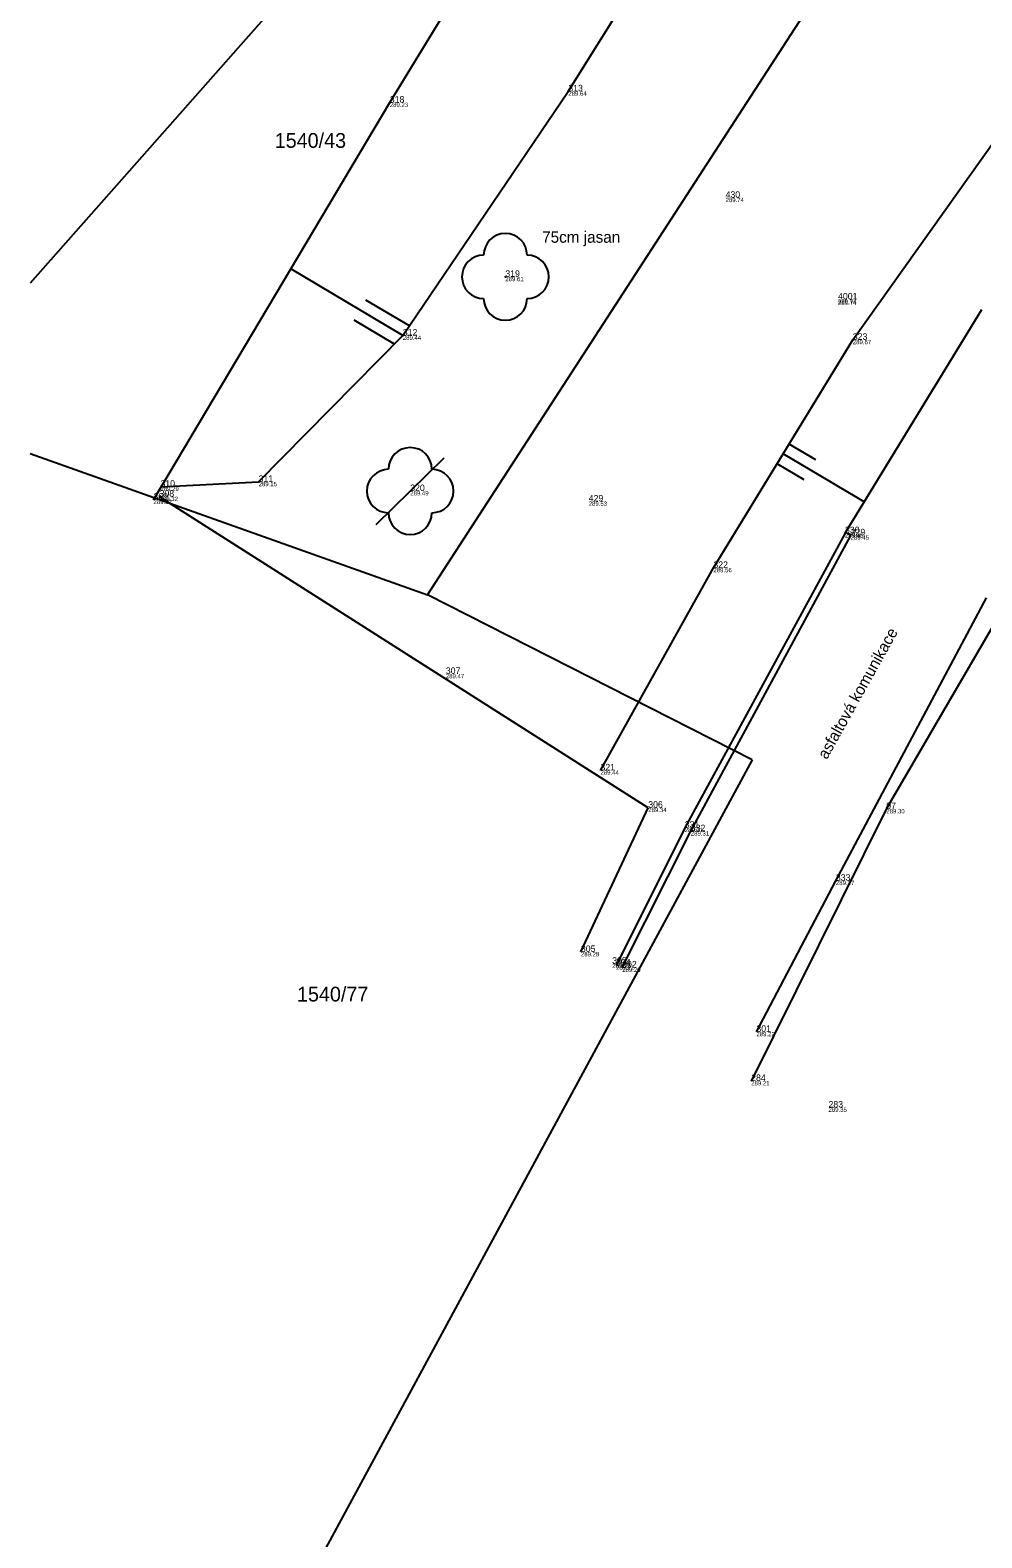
# Model space of a CAD drawing. Extents: x -805057 to -804930, y -994399 to -994240.
# Drawn here: x -805055.46 to -805033.55, y -994342.6 to -994307.89 of the extents above; entities that cross this region are included whole.
import ezdxf

# ---------------------------------------------------------------- set-up
doc = ezdxf.new("R2010")
doc.units = 0
for name, color, linetype in [('bod cislo', 7, 'Continuous'), ('bod pozice', 7, 'Continuous'), ('bod výška', 7, 'Continuous'), ('Katastralni mapa', 7, 'Continuous'), ('komunikace', 7, 'Continuous'), ('plot', 7, 'Continuous'), ('popis', 7, 'Continuous'), ('strom', 7, 'Continuous'), ('svah', 7, 'Continuous'), ('šrafy', 7, 'Continuous')]:
    doc.layers.add(name, color=color, linetype=linetype)

msp = doc.modelspace()

# ---------------------------------------------------------------- linework, layer by layer
at = {"layer": 'bod pozice'}
for p, q in [((-805043.07, -994309.3), (-805043.07, -994309.3)), ((-805047.18, -994309.56), (-805047.18, -994309.56)), ((-805039.45, -994311.75), (-805039.45, -994311.75)), ((-805044.52, -994313.57), (-805044.52, -994313.57)), ((-805036.86, -994314.09), (-805036.86, -994314.09)), ((-805033.55, -994314.32), (-805033.55, -994314.32)), ((-805046.88, -994314.92), (-805046.88, -994314.92)), ((-805036.52, -994315.02), (-805036.52, -994315.02)), ((-805052.46, -994318.4), (-805052.46, -994318.4)), ((-805050.2, -994318.29), (-805050.2, -994318.29)), ((-805052.62, -994318.7), (-805052.62, -994318.7)), ((-805052.48, -994318.63), (-805052.48, -994318.63)), ((-805046.71, -994318.5), (-805046.71, -994318.5)), ((-805042.6, -994318.74), (-805042.6, -994318.74)), ((-805036.7, -994319.47), (-805036.7, -994319.47)), ((-805036.57, -994319.52), (-805036.57, -994319.52)), ((-805039.73, -994320.27), (-805039.73, -994320.27)), ((-805045.89, -994322.71), (-805045.89, -994322.71)), ((-805042.33, -994324.93), (-805042.33, -994324.93)), ((-805041.23, -994325.79), (-805041.23, -994325.79)), ((-805035.75, -994325.82), (-805035.75, -994325.82)), ((-805040.39, -994326.25), (-805040.39, -994326.25)), ((-805040.25, -994326.33), (-805040.25, -994326.33)), ((-805036.91, -994327.47), (-805036.91, -994327.47)), ((-805042.78, -994329.11), (-805042.78, -994329.11)), ((-805042.06, -994329.38), (-805042.06, -994329.38)), ((-805041.97, -994329.42), (-805041.97, -994329.42)), ((-805041.83, -994329.47), (-805041.83, -994329.47)), ((-805038.74, -994330.95), (-805038.74, -994330.95)), ((-805038.86, -994332.08), (-805038.86, -994332.08)), ((-805037.08, -994332.69), (-805037.08, -994332.69))]:
    msp.add_line(p, q, dxfattribs=at)
at = {"layer": 'Katastralni mapa'}
for points in [[(-805037.93, -994293.88), (-805055.46, -994313.714)], [(-805046.31, -994320.89), (-805034.44, -994302.58)], [(-805055.46, -994317.638), (-805046.31, -994320.89)], [(-805038.84, -994324.69), (-805046.31, -994320.89)], [(-805038.84, -994324.69), (-805052.05, -994349.11)]]:
    msp.add_lwpolyline(points, dxfattribs=at)
at = {"layer": 'komunikace'}
for p, q in [((-805036.691, -994319.454), (-805033.55, -994314.32)), ((-805036.7, -994319.47), (-805040.39, -994326.25)), ((-805036.7, -994319.47), (-805036.691, -994319.454)), ((-805036.57, -994319.52), (-805036.691, -994319.454)), ((-805040.25, -994326.33), (-805036.57, -994319.52)), ((-805036.91, -994327.47), (-805033.44, -994320.96)), ((-805040.39, -994326.25), (-805041.97, -994329.42)), ((-805041.83, -994329.47), (-805040.25, -994326.33)), ((-805038.74, -994330.95), (-805036.91, -994327.47))]:
    msp.add_line(p, q, dxfattribs=at)
at = {"layer": 'plot'}
for p, q in [((-805047.18, -994309.56), (-805040.53, -994298.67)), ((-805052.62, -994318.7), (-805047.18, -994309.56)), ((-805031.37, -994318.3), (-805035.75, -994325.82)), ((-805041.23, -994325.79), (-805052.48, -994318.63)), ((-805042.78, -994329.11), (-805041.23, -994325.79)), ((-805035.75, -994325.82), (-805038.86, -994332.08))]:
    msp.add_line(p, q, dxfattribs=at)
at = {"layer": 'strom'}
for p, q in [((-805046.71, -994318.5), (-805045.928, -994317.732)), ((-805047.492, -994319.268), (-805046.71, -994318.5))]:
    msp.add_line(p, q, dxfattribs=at)
for centre in [(-805044.52, -994313.57), (-805046.71, -994318.5)]:
    msp.add_circle(centre, 0.0005, dxfattribs=at)
for centre, start, end in [((-805044.52, -994313.07), 0, 180), ((-805045.02, -994313.57), 90, 270), ((-805044.02, -994313.57), 270, 90), ((-805044.52, -994314.07), 180, 360), ((-805046.71, -994318), 0, 180), ((-805047.21, -994318.5), 90, 270), ((-805046.21, -994318.5), 270, 90), ((-805046.71, -994319), 180, 360)]:
    msp.add_arc(centre, 0.5, start, end, dxfattribs=at)
at = {"layer": 'svah'}
for p, q in [((-805043.07, -994309.3), (-805040.36, -994304.95)), ((-805046.88, -994314.92), (-805043.07, -994309.3)), ((-805036.52, -994315.02), (-805032.96, -994310.02)), ((-805050.2, -994318.29), (-805046.88, -994314.92)), ((-805039.73, -994320.27), (-805036.52, -994315.02)), ((-805052.46, -994318.4), (-805050.2, -994318.29)), ((-805042.33, -994324.93), (-805039.73, -994320.27))]:
    msp.add_line(p, q, dxfattribs=at)
at = {"layer": 'šrafy'}
for p, q in [((-805046.88, -994314.92), (-805049.458, -994313.388)), ((-805046.73, -994314.699), (-805047.73, -994314.105)), ((-805047.073, -994315.116), (-805048.003, -994314.564)), ((-805036.262, -994318.752), (-805038.125, -994317.645)), ((-805037.369, -994317.784), (-805037.986, -994317.418)), ((-805037.643, -994318.243), (-805038.265, -994317.873))]:
    msp.add_line(p, q, dxfattribs=at)

# ---------------------------------------------------------------- texts
at = {"layer": 'bod cislo'}
for s, p in [('318    ', (-805047.18, -994309.56)), ('313    ', (-805043.07, -994309.3)), ('430    ', (-805039.45, -994311.75)), ('319    ', (-805044.52, -994313.57)), ('4001    ', (-805036.86, -994314.09)), ('312    ', (-805046.88, -994314.92)), ('323    ', (-805036.52, -994315.02)), ('310    ', (-805052.46, -994318.4)), ('311    ', (-805050.2, -994318.29)), ('320    ', (-805046.71, -994318.5)), ('309    ', (-805052.62, -994318.7)), ('308    ', (-805052.48, -994318.63)), ('429    ', (-805042.6, -994318.74)), ('330    ', (-805036.7, -994319.47)), ('329    ', (-805036.57, -994319.52)), ('322    ', (-805039.73, -994320.27)), ('307    ', (-805045.89, -994322.71)), ('321    ', (-805042.33, -994324.93)), ('306    ', (-805041.23, -994325.79)), ('97    ', (-805035.75, -994325.82)), ('331    ', (-805040.39, -994326.25)), ('332    ', (-805040.25, -994326.33)), ('333    ', (-805036.91, -994327.47)), ('305    ', (-805042.78, -994329.11)), ('303    ', (-805042.06, -994329.38)), ('304    ', (-805041.97, -994329.42)), ('302    ', (-805041.83, -994329.47)), ('301    ', (-805038.74, -994330.95)), ('284    ', (-805038.86, -994332.08)), ('283    ', (-805037.08, -994332.69))]:
    msp.add_text(s, height=0.15, dxfattribs=at).set_placement(p)
at = {"layer": 'bod výška'}
for s, p in [('289.64  ', (-805043.07, -994309.4)), ('289.23  ', (-805047.18, -994309.66)), ('289.74  ', (-805039.45, -994311.85)), ('289.61  ', (-805044.52, -994313.67)), ('289.74  ', (-805036.86, -994314.19)), ('289.74  ', (-805036.86, -994314.22)), ('289.44  ', (-805046.88, -994315.02)), ('289.67  ', (-805036.52, -994315.12)), ('289.29  ', (-805052.46, -994318.5)), ('289.15  ', (-805050.2, -994318.39)), ('289.32  ', (-805052.62, -994318.8)), ('289.32  ', (-805052.48, -994318.73)), ('289.49  ', (-805046.71, -994318.6)), ('289.53  ', (-805042.6, -994318.84)), ('289.45  ', (-805036.7, -994319.57)), ('289.45  ', (-805036.57, -994319.62)), ('289.56  ', (-805039.73, -994320.37)), ('289.47  ', (-805045.89, -994322.81)), ('289.44  ', (-805042.33, -994325.03)), ('289.34  ', (-805041.23, -994325.89)), ('289.30  ', (-805035.75, -994325.92)), ('289.31  ', (-805040.39, -994326.35)), ('289.31  ', (-805040.25, -994326.43)), ('289.27  ', (-805036.91, -994327.57)), ('289.28  ', (-805042.78, -994329.21)), ('289.23  ', (-805042.06, -994329.48)), ('289.21  ', (-805041.97, -994329.52)), ('289.20  ', (-805041.83, -994329.57)), ('289.22  ', (-805038.74, -994331.05)), ('289.21  ', (-805038.86, -994332.18)), ('289.35  ', (-805037.08, -994332.79))]:
    msp.add_text(s, height=0.1, dxfattribs=at).set_placement(p)
at = {"layer": 'Katastralni mapa'}
msp.add_text('1540/43', height=0.34, dxfattribs=at).set_placement((-805049.83, -994310.6))
msp.add_text('1540/77', height=0.34, rotation=0.1, dxfattribs=at).set_placement((-805049.317, -994330.251))
at = {"layer": 'popis'}
msp.add_text('75cm jasan', height=0.2629, dxfattribs=at).set_placement((-805043.673, -994312.785))
msp.add_text('asfaltová komunikace', height=0.26289, rotation=60.8904, dxfattribs=at).set_placement((-805037.119, -994324.695))

doc.saveas('drawing.dxf')
